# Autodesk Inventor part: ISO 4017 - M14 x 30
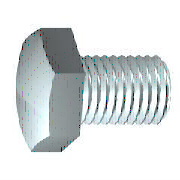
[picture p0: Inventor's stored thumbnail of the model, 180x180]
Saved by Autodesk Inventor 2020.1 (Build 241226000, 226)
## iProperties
Manager: www.cadconsulting.pl
Company: Fabian Stasiak CAD Consulting
Created: 2006-02
Part Number: ISO 4017 - M14 x 30
Material: Stal, miękka
Description: Śruba
Document SubType Name: Modeling
Standard: ISO 4017
Designer: F.Stasiak
Standards Organization: DIN
Language: pl-PL
Size Designation: M14 x 30
Categories: <MemberInstance><Categories><Category DisplayName="Mocowania" InternalName="e4da775c-781d-43d5-af7c-5136215cf5a6" Mnemonic="FSTN"><Category DisplayName="Śruby"
Density: 7.85 g/cm^3
Appearance: Stal
Mass: 61.901 g
Surface Area: 26.6487 cm^2
Volume: 7.88547 cm^3
Author: F.Stasiak
Subject: Zbiór ćwiczeń. Autodesk Inventor 2020. Kurs podstawowy
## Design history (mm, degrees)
sketch "Szkic1"
  geometry: L1 (0, 9.685)-(0, 7); L2 (6, 7)-(30, 7); L3 (30, 7)-(30, 0); L4 (30, 0)-(-0.6, 0); L5 (-3.66, 0)-(39.18, 0) reference; L6 (-0.6, 0)-(-0.6, 9.685); L7 (-0.6, 9.685)-(0, 9.685); L8 (6, 7)-(4.773, 7); L9 (4.773, 7)-(0, 7); L10 (0, -0.969)-(0, 12.591) reference
  constraints: 16 end point, 2 collinear, 2 perpendicular, 1 parallel
  dimensions: "d0" = 30 distance between parallel lines of L3 L1 (= NLG); "d1" = 24 distance from line of L2.start L3 (= GEL); "d2" = 14 diameter of L2 L4 (= GD); "d9" = 0.6001 distance between parallel lines of L6 L1 (computed from SD); "d10" = 19.37 diameter of L7 L4 (= SD2); "d13" = 1.227 distance of L2.start L8.end (computed from GAL); "d14" = 14 diameter of L9 L4 (= BDM)
revolve "Bryła" sketch "Szkic1" stored, may be unused: angle "d12" = 90 deg
sketch "Szkic2"
  geometry: L1 (0, 12.124)-(10.5, 6.062); L2 (10.5, 6.062)-(10.5, -6.062); L3 (10.5, -6.062)-(0, -12.124); L4 (0, -12.124)-(-10.5, -6.062); L5 (-10.5, -6.062)-(-10.5, 6.062); L6 (-10.5, 6.062)-(0, 12.124); 2 further points
  constraints: 12 end point, 1 coincident, 1 vertical, 11 other
  dimensions: "d11" = 21 distance between parallel lines of L5 L2 (= SW)
extrude "Głowica" join sketch "Szkic2" distance "d3" = 8.2 (= KOH - SD); taper "d4" = 0 deg
sketch "Szkic4"
  geometry: L1 (-8.8, 10.5)-(-8.8, 12.124); L2 (-8.8, 12.124)-(-7.862, 12.124); L3 (-7.862, 12.124)-(-8.8, 10.5); L4 (-9.62, 0)-(1.86, 0) reference; L5 (-0.6, 12.124)-(-8.8, 12.124) reference; L6 (-8.8, 6.062)-(-8.8, 12.124) reference
  constraints: 6 end point, 2 collinear, 1 perpendicular, 1 vertical
  dimensions: "d5" = 30 deg angle of L3 L1 (= ANG1); "d19" = 21 diameter of L1.start L4 (= SW0)
revolve "Faza1" sketch "Szkic4" stored, may be unused: angle "d21" = 90 deg
workplane "Work Plane1"
node "Bryła1"
node "Korpusy bryłowe"
node "Korpusy powierzchniowe"
feature "Gwint" dims "d15" = 24 (= GEL), "d16" = 0
chamfer "Faza2" distance "d6" = 1.2269 (= -0.5 x SPD + 0.5 x GD); stored, may be unused: second distance "d7" = 1.227 (computed from GUL), angle "d55" = 45 deg
other parameters: "NLG" = 30 [user parameter; used in 1 equation term], "GD" = 14 (= NND) [user parameter; used in 2 equation terms], "BDM" = 14 (= NND) [user parameter; used in 1 equation term], "KOH" = 8.8 [user parameter; used in 1 equation term], "GEL" = 24 [user parameter; used in 2 equation terms], "SW" = 21 [user parameter; used in 2 equation terms], "SW0" = 21 (= SW) [user parameter; used in 1 equation term], "SPD" = 11.5462 (= NND - 1.2269 x PTC) [user parameter; used in 1 equation term], "SD2" = 19.37 [user parameter; used in 2 equation terms], "SD" = 0.6 [user parameter; used in 2 equation terms], "ANG1" = 30 deg [user parameter; used in 1 equation term], "GAL" = 1.2269 (= 0.61345 x PTC) [user parameter; used in 1 equation term], "GUL" = 1.2269 (= 0.61345 x PTC) [user parameter; used in 1 equation term], "d8" = 0, "RR" = 0.6 [user parameter], "d57" = 0, "d58" = 0, "TPU" = 5 (computed from PTC) [user parameter], "GD1" = 11.5462 (= THREADDIA - 1.2269 x PTC) [user parameter], "THREADDIA" = 14 [user parameter; used in 1 equation term], "SDH" = 19.37 (= SD2) [user parameter], "SDHG" = 6 [user parameter], "TOA" = 30 deg [user parameter], "PTC" = 2 [user parameter; used in 5 equation terms], "NND" = 14 [user parameter; used in 3 equation terms], "E0" = 24.255 [user parameter]
